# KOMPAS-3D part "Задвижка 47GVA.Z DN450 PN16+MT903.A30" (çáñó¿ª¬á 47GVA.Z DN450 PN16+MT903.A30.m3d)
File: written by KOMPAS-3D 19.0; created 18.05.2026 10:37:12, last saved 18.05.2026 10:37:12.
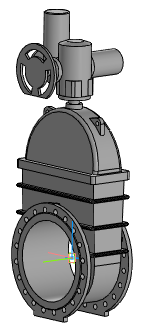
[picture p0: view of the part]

Document properties: Автор: Энергия; Полное имя файла: ..\Задвижка 47GVA.Z DN350_DN1200+MT903.A\Задвижка 47GVA.Z DN450 PN16+MT903.A30.a3d

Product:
- Part/product: Задвижка 47GVA.Z DN450 PN16+MT903.A30
    Масса: 923.459
  - Body: Электропривод МТ903.А30 без блока управления
      Масса: 163.268
  - Body: Задвижка 47GVA.Z DN450 PN16 без исполнит. мех.
      Масса: 760.191

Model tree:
1. Операция без истории:1
2. Операция без истории:2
